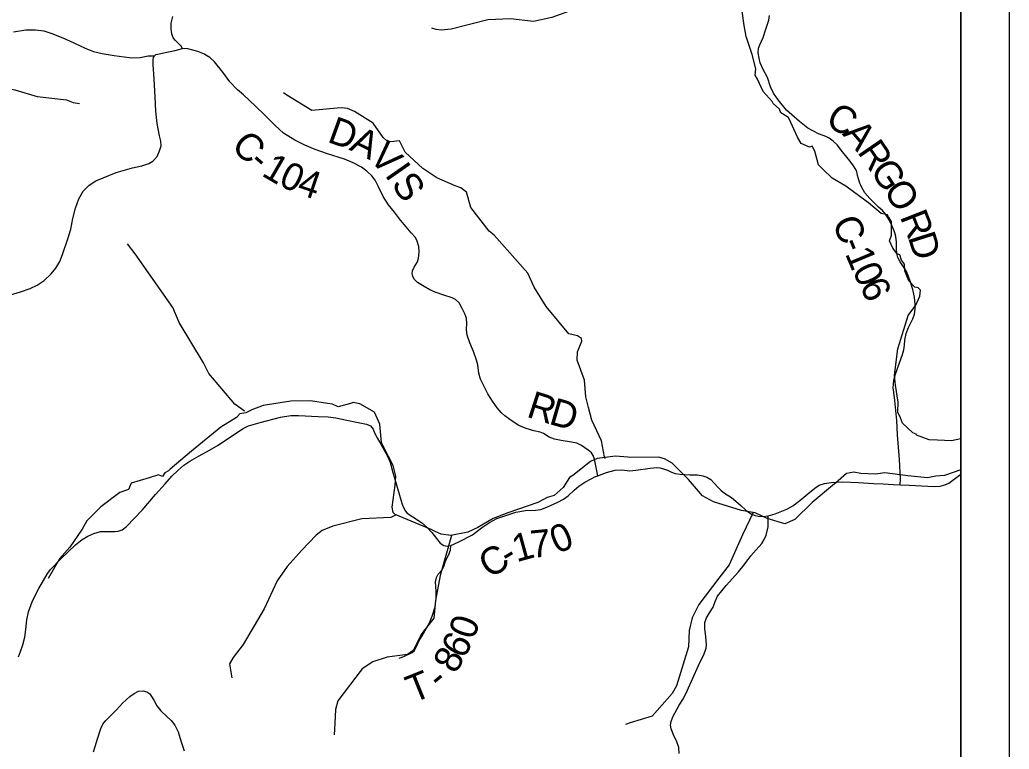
# Model space of a CAD drawing. Extents: x -1.8 to 75.7, y -2 to 25.
# Drawn here: x 48.65 to 50.7, y 17.082 to 18.595 of the extents above; entities that cross this region are included whole.
import ezdxf

# ---------------------------------------------------------------- set-up
doc = ezdxf.new("R2010")
doc.units = 0
for name, color, linetype in [('GM_X_County_Road', 7, 'Continuous'), ('GM_X_County_Road_Text', 7, 'Continuous'), ('GM_X_Minor_River', 7, 'Continuous'), ('GM_X_Township', 7, 'Continuous'), ('GM_X_Township_Road', 7, 'Continuous'), ('GM_X_Township_Road_Text', 7, 'Continuous'), ('SH_Data', 7, 'Continuous')]:
    doc.layers.add(name, color=color, linetype=linetype)

msp = doc.modelspace()

# ---------------------------------------------------------------- linework, layer by layer
at = {"layer": 'GM_X_County_Road'}
for points in [[(49.0352, 18.5218), (49.0327, 18.5234), (49.0189, 18.5288), (48.9979, 18.5348), (48.9873, 18.5352), (48.9843, 18.5403), (48.9787, 18.546), (48.9725, 18.5519), (48.9681, 18.5573), (48.9649, 18.5661), (48.9634, 18.5763), (48.9639, 18.588), (48.9669, 18.6019)], [(50.3068, 18.3578), (50.3066, 18.3579), (50.2931, 18.3646), (50.2832, 18.3705), (50.2656, 18.3838), (50.2497, 18.3978), (50.239, 18.4074), (50.2213, 18.429), (50.2118, 18.4425), (50.2057, 18.4558), (50.1991, 18.475), (50.1904, 18.4919), (50.1838, 18.5059), (50.1818, 18.5154), (50.1803, 18.5262), (50.1806, 18.536), (50.1832, 18.5431), (50.1902, 18.558), (50.1958, 18.5752), (50.2022, 18.5938), (50.2035, 18.6038)], [(49.8478, 17.6496), (49.8451, 17.6631), (49.8411, 17.6835), (49.8384, 17.6911), (49.8343, 17.6968), (49.8274, 17.7027), (49.8139, 17.7122), (49.8041, 17.7169), (49.793, 17.7189), (49.7717, 17.7228), (49.7577, 17.725), (49.7469, 17.7297), (49.7354, 17.7368), (49.7282, 17.7395), (49.7152, 17.7429), (49.6995, 17.7471), (49.6838, 17.7535), (49.6703, 17.7625), (49.6548, 17.7738), (49.6477, 17.7805), (49.6391, 17.7903), (49.6298, 17.804), (49.6197, 17.8192), (49.6124, 17.8342), (49.6048, 17.8497), (49.6013, 17.8622), (49.5991, 17.8791), (49.5964, 17.8889), (49.5898, 17.9073), (49.5824, 17.9248), (49.5768, 17.9412), (49.5758, 17.9525), (49.5766, 17.9653), (49.5753, 17.9756), (49.5729, 17.9839), (49.5667, 17.9962), (49.5601, 18.0082), (49.553, 18.0146), (49.5456, 18.0183), (49.5289, 18.0237), (49.511, 18.0298), (49.4997, 18.0352), (49.4879, 18.0418), (49.474, 18.0502), (49.4678, 18.0563), (49.4641, 18.0627), (49.4632, 18.0686), (49.4639, 18.0742), (49.4673, 18.0819), (49.474, 18.0931), (49.4759, 18.1005), (49.4776, 18.1128), (49.4771, 18.1248), (49.4735, 18.1361), (49.4697, 18.1433), (49.461, 18.1533), (49.4509, 18.1658), (49.4391, 18.1795), (49.4261, 18.1957), (49.4143, 18.2114), (49.4028, 18.2286), (49.3937, 18.2468), (49.3866, 18.2623), (49.3795, 18.2711), (49.3692, 18.2807), (49.3579, 18.289), (49.3407, 18.2986), (49.323, 18.3057), (49.2879, 18.3167), (49.2617, 18.3258), (49.2403, 18.3347), (49.2197, 18.3452), (49.1966, 18.3599), (49.1792, 18.3759), (49.1576, 18.397), (49.1384, 18.4157), (49.1132, 18.4392), (49.1011, 18.4498), (49.0852, 18.4665), (49.0705, 18.4863), (49.0533, 18.5074), (49.0437, 18.5165), (49.0352, 18.5218)], [(50.392, 18.2531), (50.3907, 18.2559), (50.3879, 18.265), (50.3861, 18.272), (50.3844, 18.2801), (50.3811, 18.2868), (50.3774, 18.292), (50.37, 18.3027), (50.355, 18.3213), (50.3434, 18.3359), (50.3354, 18.3433), (50.3268, 18.3496), (50.3199, 18.3527), (50.3068, 18.3578)], [(50.4743, 17.6308), (50.4751, 17.6431), (50.4725, 17.6832), (50.469, 17.7344), (50.4672, 17.7641), (50.4629, 17.8055), (50.4609, 17.8227), (50.46, 17.8319), (50.4601, 17.8384), (50.4614, 17.8476), (50.4644, 17.8602), (50.4725, 17.8833), (50.4792, 17.9005), (50.4816, 17.9103), (50.4829, 17.9202), (50.484, 17.9308), (50.4868, 17.9444), (50.4917, 17.9566), (50.5008, 17.9746), (50.5041, 17.9845), (50.5056, 17.9949), (50.5056, 18.0047), (50.5037, 18.02), (50.5002, 18.0355), (50.4964, 18.0486), (50.491, 18.0645), (50.4866, 18.0741), (50.4742, 18.093), (50.4694, 18.1022), (50.467, 18.11), (50.4666, 18.1201), (50.4668, 18.134), (50.4653, 18.1453), (50.4627, 18.1551), (50.4579, 18.1669), (50.4513, 18.1804), (50.4437, 18.1918), (50.4376, 18.1991), (50.4293, 18.2066), (50.4114, 18.2242), (50.4012, 18.2362), (50.3947, 18.2472), (50.392, 18.2531)], [(48.6475, 17.2738), (48.6517, 17.2853), (48.6563, 17.2989), (48.6605, 17.3146), (48.6627, 17.3305), (48.6647, 17.3508), (48.6682, 17.367), (48.6764, 17.3902), (48.6892, 17.4155), (48.7064, 17.4451), (48.7126, 17.4544), (48.736, 17.478), (48.7654, 17.5061), (48.7789, 17.5171), (48.791, 17.524), (48.8034, 17.5297), (48.8173, 17.5335), (48.8325, 17.5337), (48.8471, 17.5341), (48.8535, 17.5346), (48.8621, 17.537), (48.871, 17.5439), (48.9037, 17.5783), (48.9315, 17.6105), (48.9509, 17.6328), (48.965, 17.6485), (48.9772, 17.66), (48.9896, 17.6711), (49.0024, 17.6797), (49.0218, 17.6907), (49.0428, 17.7024), (49.0609, 17.713), (49.0925, 17.734), (49.1126, 17.7472), (49.124, 17.7528), (49.1481, 17.7596), (49.1903, 17.7706), (49.2113, 17.7744), (49.2278, 17.7743), (49.268, 17.7724), (49.2891, 17.7716), (49.3049, 17.7697), (49.3277, 17.7645), (49.348, 17.7603), (49.3684, 17.7562), (49.3768, 17.753), (49.3819, 17.7463), (49.3846, 17.74), (49.3905, 17.7282), (49.3979, 17.7152), (49.4121, 17.6901), (49.4168, 17.6791), (49.4188, 17.6721), (49.4227, 17.6563), (49.4293, 17.6351), (49.4394, 17.5998), (49.4428, 17.5883), (49.4482, 17.577), (49.4529, 17.5718), (49.4646, 17.5642), (49.4821, 17.5527), (49.4941, 17.5424), (49.5037, 17.5316), (49.5135, 17.5193), (49.5211, 17.5097), (49.5284, 17.5048), (49.5353, 17.5036), (49.5429, 17.5046), (49.5596, 17.5124), (49.5883, 17.5272), (49.6067, 17.5412), (49.6232, 17.5527), (49.6386, 17.5605), (49.6779, 17.574), (49.6976, 17.5775), (49.7184, 17.5782), (49.7295, 17.5797), (49.742, 17.5844), (49.7648, 17.5947), (49.7763, 17.6006), (49.7862, 17.6077), (49.7987, 17.6197), (49.8085, 17.6278), (49.821, 17.6361), (49.8338, 17.6433), (49.8414, 17.6469), (49.8478, 17.6496), (49.8654, 17.656), (49.8838, 17.6612), (49.8978, 17.6614), (49.9138, 17.6595), (49.9268, 17.6607), (49.9562, 17.6649), (49.97, 17.6663), (49.9761, 17.6658), (49.9835, 17.6639), (49.9918, 17.6609), (50.0007, 17.6568), (50.008, 17.6543), (50.0186, 17.6524), (50.0384, 17.6516), (50.0544, 17.6511), (50.0653, 17.6496), (50.0738, 17.6464), (50.0818, 17.6416), (50.0884, 17.6346), (50.0977, 17.6246), (50.1028, 17.6197), (50.1104, 17.6136), (50.1245, 17.6043), (50.1335, 17.5967), (50.1439, 17.5875), (50.1546, 17.5781), (50.1664, 17.5698), (50.1738, 17.5672), (50.1797, 17.5655), (50.1902, 17.5646), (50.2005, 17.566), (50.2152, 17.5705), (50.2396, 17.5801), (50.2518, 17.5873), (50.2662, 17.598), (50.2826, 17.6117), (50.2974, 17.6235), (50.3063, 17.6296), (50.3172, 17.6335), (50.3312, 17.6357), (50.3552, 17.6368), (50.3877, 17.6354), (50.4189, 17.6333), (50.4387, 17.6324), (50.4594, 17.6313), (50.4743, 17.6308), (50.4928, 17.6299), (50.5314, 17.6277), (50.5457, 17.6268), (50.5568, 17.6275), (50.5669, 17.6303), (50.5748, 17.6341), (50.5863, 17.6423), (50.6002, 17.6527)], [(50.0164, 17.0734), (50.0155, 17.0857), (50.0107, 17.0995), (50.006, 17.1088), (49.9997, 17.1245), (49.9984, 17.1324), (49.9997, 17.1401), (50.003, 17.1495), (50.0164, 17.1735), (50.0254, 17.1875), (50.0328, 17.2035), (50.0561, 17.256), (50.0684, 17.2805), (50.0719, 17.2919), (50.0728, 17.2996), (50.0717, 17.3154), (50.0695, 17.3328), (50.0697, 17.345), (50.0728, 17.3547), (50.0791, 17.3655), (50.0866, 17.3771), (50.0908, 17.3885), (50.0954, 17.3999), (50.1138, 17.4221), (50.1391, 17.4499), (50.1507, 17.4644), (50.1647, 17.4835), (50.1755, 17.496), (50.1878, 17.5087), (50.1926, 17.5171), (50.1965, 17.5265), (50.2005, 17.5436), (50.2009, 17.5564), (50.2005, 17.566)], [(48.8029, 17.077), (48.8064, 17.0878), (48.8109, 17.1038), (48.8177, 17.1251), (48.8224, 17.1344), (48.8283, 17.1417), (48.8504, 17.1638), (48.8629, 17.1777), (48.8783, 17.1916), (48.8872, 17.1979), (48.8959, 17.2026), (48.9054, 17.2035), (48.913, 17.2013), (48.9197, 17.197), (48.9275, 17.1842), (48.9338, 17.1725), (48.942, 17.1621), (48.9548, 17.1502), (48.9635, 17.1422), (48.9715, 17.132), (48.978, 17.1186), (48.9834, 17.0995), (48.9906, 17.0793)]]:
    msp.add_lwpolyline(points, dxfattribs=at)
at = {"layer": 'GM_X_Minor_River'}
for points in [[(50.0515, 18.8383), (49.9893, 18.8372), (49.9616, 18.829), (49.8841, 18.7839), (49.8639, 18.7647), (49.8379, 18.7371), (49.8303, 18.7242), (49.8171, 18.6741), (49.804, 18.6335), (49.7987, 18.6225), (49.7872, 18.6123), (49.7523, 18.5993), (49.7147, 18.5911), (49.667, 18.5968), (49.62, 18.5948), (49.5441, 18.5755), (49.5232, 18.5737), (49.5126, 18.5746), (49.5035, 18.5773)], [(50.6002, 17.7263), (50.5808, 17.7218), (50.5513, 17.7229), (50.5343, 17.7236), (50.5082, 17.7338), (50.5075, 17.7357), (50.5007, 17.7384), (50.4791, 17.7588), (50.4749, 17.7695), (50.4696, 17.7812), (50.47, 17.8021), (50.4643, 17.8371), (50.4628, 17.858), (50.4691, 17.9124), (50.4906, 17.9816), (50.5065, 18.0029), (50.5151, 18.0216), (50.5166, 18.0345), (50.5113, 18.0394), (50.5045, 18.0405), (50.4921, 18.0534), (50.4905, 18.0572), (50.4841, 18.0743), (50.4833, 18.088), (50.4773, 18.0967), (50.4735, 18.1074), (50.4678, 18.1096), (50.4587, 18.1214), (50.4523, 18.1366), (50.4564, 18.1484), (50.4564, 18.1765), (50.45, 18.1864), (50.4477, 18.1905), (50.4348, 18.1935), (50.4084, 18.2152), (50.4038, 18.2189), (50.3618, 18.2496), (50.3335, 18.2667), (50.3142, 18.2852), (50.3047, 18.294), (50.2975, 18.3225), (50.2918, 18.3331), (50.2865, 18.3308), (50.2688, 18.3387), (50.2616, 18.3516), (50.2475, 18.3816), (50.2426, 18.3926), (50.2271, 18.4021), (50.2241, 18.4093), (50.2108, 18.4215), (50.2089, 18.4253), (50.19, 18.4461), (50.1787, 18.4716), (50.1737, 18.4803), (50.1749, 18.4932), (50.1676, 18.5228), (50.1548, 18.5604), (50.151, 18.5829), (50.1471, 18.6125)], [(48.3577, 18.5354), (48.3905, 18.5445), (48.4337, 18.5347), (48.4873, 18.5065), (48.5228, 18.4814), (48.568, 18.4625), (48.6398, 18.4496), (48.6858, 18.4356), (48.7469, 18.4287), (48.7607, 18.4237), (48.7739, 18.421)], [(49.8633, 17.6852), (49.8618, 17.6889), (49.8556, 17.7221), (49.8354, 17.7649), (49.8286, 17.791), (49.8232, 17.8131), (49.8201, 17.8474), (49.8048, 17.8893), (49.8053, 17.9067), (49.8146, 17.9285), (49.8137, 17.9342), (49.8059, 17.9394), (49.7875, 17.9438), (49.7405, 18.0007), (49.716, 18.0402), (49.7025, 18.0695), (49.6327, 18.1484), (49.6223, 18.1564), (49.5849, 18.2058), (49.5757, 18.2372), (49.5642, 18.2467), (49.5519, 18.2505), (49.5138, 18.2673), (49.4849, 18.2864), (49.4485, 18.3203), (49.4368, 18.3438), (49.4186, 18.3421), (49.4107, 18.3439), (49.403, 18.3506), (49.3823, 18.3805), (49.3437, 18.4045), (49.3292, 18.4107), (49.3164, 18.4122), (49.3073, 18.4117), (49.255, 18.4066), (49.203, 18.4386), (49.1967, 18.4437)], [(49.1155, 17.7834), (49.0955, 17.7977), (49.0415, 17.8613), (49.0304, 17.8833), (48.9804, 17.9669), (48.967, 17.9981), (48.8891, 18.1096), (48.8731, 18.1306)], [(50.6002, 17.6616), (50.5658, 17.65), (50.5484, 17.6484), (50.5306, 17.6449), (50.4902, 17.6494), (50.4425, 17.6554), (50.4229, 17.6527), (50.393, 17.6541), (50.3783, 17.6571), (50.3628, 17.654), (50.3405, 17.6342), (50.3382, 17.6327), (50.2918, 17.5942), (50.2559, 17.5588), (50.2351, 17.55), (50.1984, 17.5609), (50.1735, 17.5723), (50.1451, 17.5775), (50.0872, 17.5953), (50.0646, 17.6077), (50.0354, 17.6415), (50.0017, 17.6753), (49.9862, 17.6847), (49.9738, 17.6877), (49.9133, 17.6876), (49.9099, 17.6883), (49.8842, 17.6898), (49.8464, 17.6852), (49.8328, 17.679), (49.7957, 17.6497), (49.7893, 17.6455), (49.7761, 17.625), (49.7572, 17.6086), (49.7425, 17.6043), (49.7236, 17.594), (49.6612, 17.5722), (49.6306, 17.5608), (49.5989, 17.5424), (49.5785, 17.5325), (49.5433, 17.5256), (49.5233, 17.5282), (49.5104, 17.5335), (49.5025, 17.5377), (49.4276, 17.569), (49.4238, 17.5732), (49.4216, 17.5846), (49.4279, 17.6299), (49.4294, 17.6489), (49.4234, 17.6705), (49.4044, 17.7081), (49.3995, 17.7183), (49.3957, 17.7563), (49.3847, 17.781), (49.3544, 17.7988), (49.3408, 17.8011), (49.3355, 17.7991), (49.3095, 17.7922), (49.2977, 17.7979), (49.2875, 17.799), (49.2524, 17.805), (49.2119, 17.8038), (49.1545, 17.7949), (49.1307, 17.7861), (49.1182, 17.7796), (49.1057, 17.7781), (49.0993, 17.7705), (49.0664, 17.7499), (49.0056, 17.7003), (48.9614, 17.663), (48.958, 17.6599), (48.9508, 17.6557), (48.9459, 17.6481), (48.9376, 17.6512), (48.918, 17.6454), (48.8806, 17.6339), (48.8753, 17.621), (48.8571, 17.6149), (48.8178, 17.5847), (48.7888, 17.5562), (48.779, 17.5387), (48.754, 17.501), (48.7325, 17.4774), (48.7087, 17.4367)], [(50.1699, 17.5729), (50.1476, 17.5267), (50.1196, 17.465), (50.0983, 17.4368), (50.057, 17.3827), (50.0429, 17.3547), (50.0368, 17.3286), (50.0358, 17.2945), (50.0107, 17.2137), (50.0019, 17.1976), (49.96, 17.1507), (49.9146, 17.137), (49.9054, 17.1339)], [(49.4296, 17.5682), (49.4188, 17.5629), (49.3585, 17.5599), (49.2989, 17.545), (49.2765, 17.5357), (49.2639, 17.5263), (49.2338, 17.4945), (49.2037, 17.4613), (49.1831, 17.4317), (49.1566, 17.3738), (49.1126, 17.2995), (49.092, 17.2723), (49.0843, 17.2594), (49.0891, 17.2305)], [(49.5445, 17.5258), (49.5209, 17.4423), (49.5114, 17.3906), (49.5077, 17.3543), (49.4833, 17.3224), (49.4652, 17.2869), (49.4532, 17.2786), (49.4111, 17.2735), (49.3813, 17.2638), (49.3597, 17.2493), (49.3089, 17.1826), (49.3039, 17.1649), (49.3026, 17.1361), (49.3011, 17.1122)]]:
    msp.add_lwpolyline(points, dxfattribs=at)
at = {"layer": 'GM_X_Township'}
msp.add_lwpolyline([(47.7632, 15.7121), (50.6002, 15.7121), (50.6002, 18.6397)], dxfattribs=at)
at = {"layer": 'GM_X_Township_Road'}
for points in [[(48.6372, 18.5699), (48.6622, 18.5741), (48.6827, 18.5741), (48.7001, 18.5718), (48.7163, 18.5666), (48.7392, 18.5574), (48.7623, 18.5472), (48.7852, 18.5363), (48.8028, 18.5292), (48.821, 18.5251), (48.8456, 18.5206), (48.866, 18.5178), (48.8822, 18.5163), (48.8991, 18.5168), (48.9158, 18.52), (48.9293, 18.5204)], [(48.6235, 18.0225), (48.6515, 18.0306), (48.6718, 18.0375), (48.6862, 18.0447), (48.7003, 18.0546), (48.7151, 18.0681), (48.7247, 18.0798), (48.733, 18.094), (48.7386, 18.1081), (48.7499, 18.1425), (48.7555, 18.1609), (48.76, 18.1828), (48.7651, 18.2042), (48.772, 18.2238), (48.781, 18.2395), (48.7936, 18.2523), (48.8073, 18.2611), (48.8225, 18.2675), (48.8494, 18.278), (48.8835, 18.2876), (48.9031, 18.2921), (48.9171, 18.297), (48.926, 18.3019), (48.9348, 18.3116), (48.9395, 18.3233), (48.9429, 18.3336), (48.9421, 18.3429), (48.9397, 18.3542), (48.9344, 18.3798), (48.932, 18.4051), (48.9303, 18.435), (48.9283, 18.4716), (48.9264, 18.502), (48.9266, 18.5124), (48.9271, 18.517), (48.9293, 18.5204), (48.9322, 18.5226), (48.9362, 18.5236), (48.9509, 18.5273), (48.9718, 18.5315), (48.9873, 18.5352)], [(49.4359, 17.2714), (49.446, 17.2744), (49.4629, 17.2827), (49.4678, 17.2871), (49.4718, 17.2955), (49.4771, 17.3065), (49.4835, 17.3173), (49.4992, 17.3441), (49.5046, 17.3581), (49.5105, 17.3779), (49.5127, 17.3959), (49.513, 17.4101), (49.512, 17.4189), (49.5115, 17.4297), (49.5132, 17.4383), (49.5172, 17.4457), (49.525, 17.4543), (49.5294, 17.4633), (49.5319, 17.4727), (49.539, 17.4864), (49.5422, 17.4948), (49.5429, 17.5046)]]:
    msp.add_lwpolyline(points, dxfattribs=at)
at = {"layer": 'SH_Data'}
for p, q in [((50.7002, 22.6121), (50.7002, 15.6121)), ((50.6002, 22.5121), (50.6002, 15.7121)), ((50.6002, 22.5121), (50.6002, 15.7121))]:
    msp.add_line(p, q, dxfattribs=at)

# ---------------------------------------------------------------- texts
at = {"layer": 'GM_X_County_Road_Text'}
for s, rotation, p in [('C', 329.1581, (50.3166, 18.3785)), ('D', 340.0016, (49.2852, 18.3424)), ('A', 310.3338, (50.3529, 18.3578)), ('C', 315.2926, (49.0857, 18.3306)), ('A', 333.7917, (49.3307, 18.3259)), ('V', 314.687, (49.3715, 18.3068)), ('R', 304.3959, (50.3843, 18.3209)), ('-', 318.6757, (49.1215, 18.2952)), ('1', 329.9072, (49.1489, 18.2727)), ('0', 334.9905, (49.184, 18.2526)), ('I', 305.0173, (49.405, 18.2732)), ('G', 303.4335, (50.4105, 18.2826)), ('4', 341.0668, (49.2219, 18.2354)), ('S', 304.5862, (49.4183, 18.2541)), ('O', 303.194, (50.4381, 18.2409)), ('C', 292.4711, (50.3325, 18.1752)), ('R', 291.5072, (50.473, 18.1868)), ('D', 287.6504, (50.4898, 18.1444)), ('-', 292.5162, (50.3504, 18.132)), ('1', 292.6769, (50.3594, 18.1103)), ('0', 295.4696, (50.3741, 18.0753)), ('6', 295.758, (50.3893, 18.0434)), ('R', 342.1118, (49.698, 17.7723)), ('D', 343.9296, (49.7443, 17.7574)), ('0', 22.8253, (49.7633, 17.4868)), ('1', 15.4032, (49.6792, 17.4699)), ('7', 5.6189, (49.7105, 17.4788)), ('C', 32.0401, (49.6236, 17.435)), ('-', 30.8138, (49.6629, 17.4596))]:
    msp.add_text(s, height=0.0568, rotation=rotation, dxfattribs=at).set_placement(p)
at = {"layer": 'GM_X_Township_Road_Text'}
for s, rotation, p in [('0', 70.935, (49.5908, 17.3077)), ('6', 61.4261, (49.5699, 17.2675)), ('8', 62.0232, (49.5536, 17.2368)), ('T', 21.8814, (49.4647, 17.1775)), ('-', 39.982, (49.5208, 17.2034))]:
    msp.add_text(s, height=0.0568, rotation=rotation, dxfattribs=at).set_placement(p)

doc.saveas('drawing.dxf')
